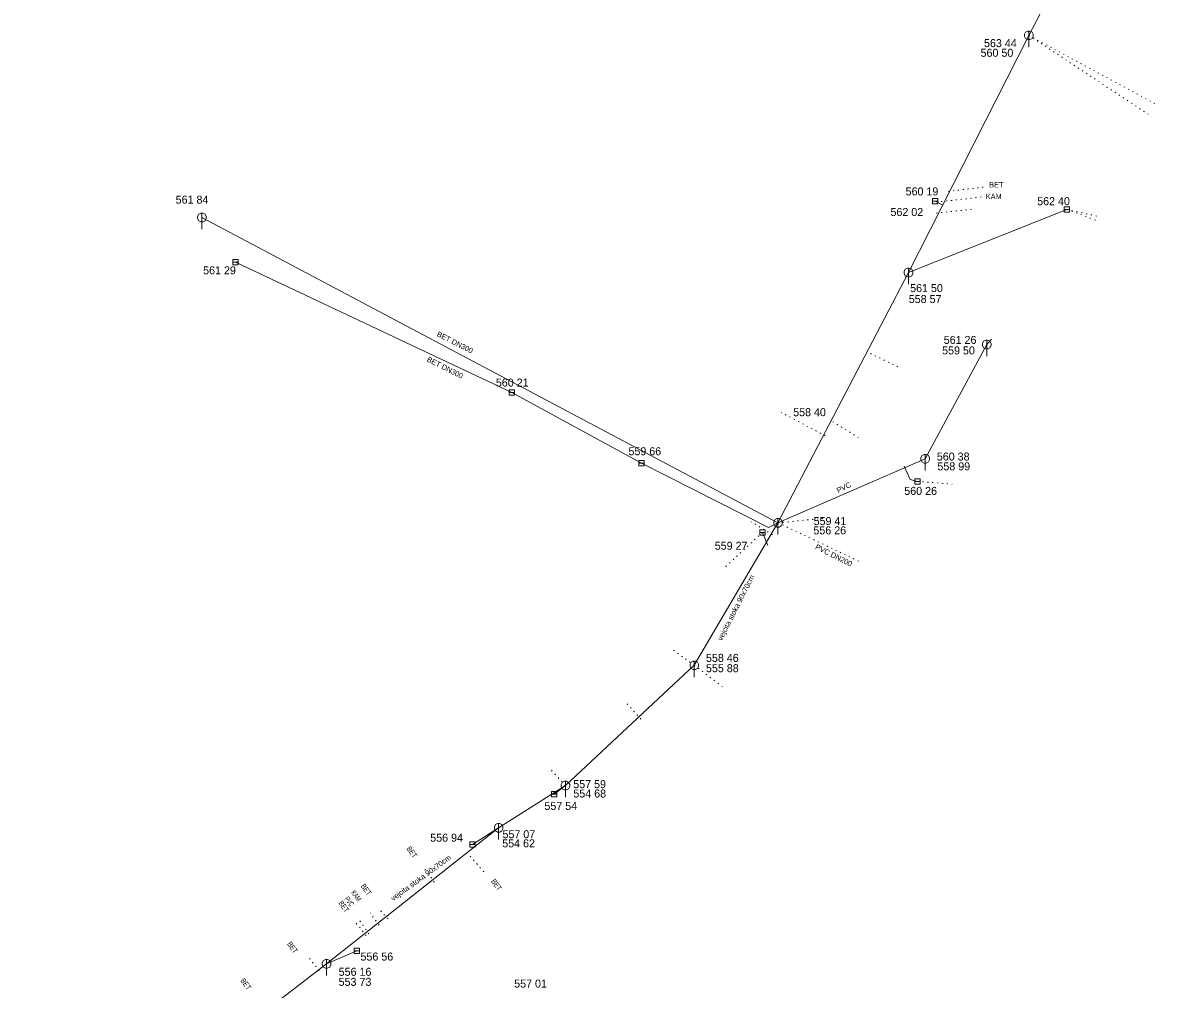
# Model space of a CAD drawing. Extents: x -710806 to -710046, y -1116920 to -1116046.
# Drawn here: x -710401.2 to -710295, y -1116469 to -1116378.5 of the extents above; entities that cross this region are included whole.
import ezdxf
from ezdxf.enums import TextEntityAlignment as Align

# ---------------------------------------------------------------- set-up
doc = ezdxf.new("R2010")
doc.units = 0
doc.header["$LTSCALE"] = 0.3
doc.linetypes.add('DOTTED', pattern=[1.5, 0.3, -1.2])
for name, color, linetype, lineweight in [('40', 7, 'Continuous', 13), ('41', 7, 'Continuous', 13), ('45', 7, 'DOTTED', 13)]:
    doc.layers.add(name, color=color, linetype=linetype, lineweight=lineweight)
doc.layers.add('43', color=7, linetype='Continuous')
doc.layers.add('44', color=7, linetype='Continuous')

msp = doc.modelspace()

# ---------------------------------------------------------------- linework, layer by layer
at = {"layer": '40'}
for points in [[(-710330.414, -1116425.31), (-710318.181, -1116401.863), (-710306.903, -1116379.643), (-710298.116, -1116362.85), (-710302.211, -1116354.462), (-710301.898, -1116344.085), (-710299.298, -1116328.891)], [(-710350.334, -1116449.934), (-710338.256, -1116438.666), (-710330.414, -1116425.31), (-710384.403, -1116396.708)], [(-710381.248, -1116400.906), (-710355.346, -1116413.11), (-710343.193, -1116419.719), (-710331.29, -1116425.767), (-710330.414, -1116425.31), (-710316.618, -1116419.317), (-710310.847, -1116408.606), (-710310.408, -1116408.122)], [(-710401.2, -1116488.589), (-710372.719, -1116466.635), (-710356.594, -1116453.887), (-710350.334, -1116449.934)]]:
    msp.add_lwpolyline(points, dxfattribs=at)
at = {"layer": '41'}
for p, q in [((-710306.903, -1116379.243), (-710306.903, -1116380.743)), ((-710315.418, -1116394.944), (-710315.918, -1116394.944)), ((-710315.918, -1116394.944), (-710315.918, -1116395.444)), ((-710315.418, -1116395.444), (-710315.418, -1116394.944)), ((-710315.418, -1116395.194), (-710315.918, -1116395.194)), ((-710315.918, -1116395.444), (-710315.418, -1116395.444)), ((-710303.083, -1116395.705), (-710303.583, -1116395.705)), ((-710303.583, -1116395.705), (-710303.583, -1116396.205)), ((-710303.083, -1116395.955), (-710303.583, -1116395.955)), ((-710303.083, -1116396.205), (-710303.083, -1116395.705)), ((-710384.403, -1116396.308), (-710384.403, -1116397.808)), ((-710303.583, -1116396.205), (-710303.083, -1116396.205)), ((-710380.998, -1116400.656), (-710381.498, -1116400.656)), ((-710381.498, -1116400.656), (-710381.498, -1116401.156)), ((-710380.998, -1116400.906), (-710381.498, -1116400.906)), ((-710381.498, -1116401.156), (-710380.998, -1116401.156)), ((-710380.998, -1116401.156), (-710380.998, -1116400.656)), ((-710318.181, -1116401.463), (-710318.181, -1116402.963)), ((-710310.847, -1116408.206), (-710310.847, -1116409.706)), ((-710355.096, -1116412.86), (-710355.596, -1116412.86)), ((-710355.596, -1116412.86), (-710355.596, -1116413.36)), ((-710355.096, -1116413.11), (-710355.596, -1116413.11)), ((-710355.096, -1116413.36), (-710355.096, -1116412.86)), ((-710355.596, -1116413.36), (-710355.096, -1116413.36)), ((-710342.943, -1116419.469), (-710343.443, -1116419.469)), ((-710343.443, -1116419.469), (-710343.443, -1116419.969)), ((-710342.943, -1116419.969), (-710342.943, -1116419.469)), ((-710316.618, -1116418.917), (-710316.618, -1116420.417)), ((-710342.943, -1116419.719), (-710343.443, -1116419.719)), ((-710343.443, -1116419.969), (-710342.943, -1116419.969)), ((-710317.087, -1116421.193), (-710317.587, -1116421.193)), ((-710317.587, -1116421.193), (-710317.587, -1116421.693)), ((-710317.087, -1116421.443), (-710317.587, -1116421.443)), ((-710317.087, -1116421.693), (-710317.087, -1116421.193)), ((-710317.587, -1116421.693), (-710317.087, -1116421.693)), ((-710330.414, -1116424.91), (-710330.414, -1116426.41)), ((-710331.62, -1116425.959), (-710332.12, -1116425.959)), ((-710332.12, -1116425.959), (-710332.12, -1116426.459)), ((-710331.62, -1116426.209), (-710332.12, -1116426.209)), ((-710332.12, -1116426.459), (-710331.62, -1116426.459)), ((-710331.62, -1116426.459), (-710331.62, -1116425.959)), ((-710338.256, -1116438.266), (-710338.256, -1116439.766)), ((-710350.334, -1116449.534), (-710350.334, -1116451.034)), ((-710351.141, -1116450.499), (-710351.641, -1116450.499)), ((-710351.641, -1116450.499), (-710351.641, -1116450.999)), ((-710351.141, -1116450.749), (-710351.641, -1116450.749)), ((-710351.641, -1116450.999), (-710351.141, -1116450.999)), ((-710351.141, -1116450.999), (-710351.141, -1116450.499)), ((-710356.594, -1116453.487), (-710356.594, -1116454.987)), ((-710358.804, -1116455.195), (-710359.304, -1116455.195)), ((-710359.304, -1116455.195), (-710359.304, -1116455.695)), ((-710358.804, -1116455.445), (-710359.304, -1116455.445)), ((-710358.804, -1116455.695), (-710358.804, -1116455.195)), ((-710359.304, -1116455.695), (-710358.804, -1116455.695)), ((-710369.625, -1116465.17), (-710370.125, -1116465.17)), ((-710370.125, -1116465.17), (-710370.125, -1116465.67)), ((-710369.625, -1116465.42), (-710370.125, -1116465.42)), ((-710370.125, -1116465.67), (-710369.625, -1116465.67)), ((-710369.625, -1116465.67), (-710369.625, -1116465.17)), ((-710372.719, -1116466.235), (-710372.719, -1116467.735))]:
    msp.add_line(p, q, dxfattribs=at)
for points in [[(-710307.303, -1116379.743), (-710307.303, -1116379.543), (-710307.203, -1116379.343), (-710307.003, -1116379.243), (-710306.803, -1116379.243), (-710306.603, -1116379.343), (-710306.503, -1116379.543), (-710306.503, -1116379.743), (-710306.603, -1116379.943), (-710306.803, -1116380.043), (-710307.003, -1116380.043), (-710307.203, -1116379.943)], [(-710384.803, -1116396.808), (-710384.803, -1116396.608), (-710384.703, -1116396.408), (-710384.503, -1116396.308), (-710384.303, -1116396.308), (-710384.103, -1116396.408), (-710384.003, -1116396.608), (-710384.003, -1116396.808), (-710384.103, -1116397.008), (-710384.303, -1116397.108), (-710384.503, -1116397.108), (-710384.703, -1116397.008)], [(-710318.581, -1116401.963), (-710318.581, -1116401.763), (-710318.481, -1116401.563), (-710318.281, -1116401.463), (-710318.081, -1116401.463), (-710317.881, -1116401.563), (-710317.781, -1116401.763), (-710317.781, -1116401.963), (-710317.881, -1116402.163), (-710318.081, -1116402.263), (-710318.281, -1116402.263), (-710318.481, -1116402.163)], [(-710311.247, -1116408.706), (-710311.247, -1116408.506), (-710311.147, -1116408.306), (-710310.947, -1116408.206), (-710310.747, -1116408.206), (-710310.547, -1116408.306), (-710310.447, -1116408.506), (-710310.447, -1116408.706), (-710310.547, -1116408.906), (-710310.747, -1116409.006), (-710310.947, -1116409.006), (-710311.147, -1116408.906)], [(-710317.018, -1116419.417), (-710317.018, -1116419.217), (-710316.918, -1116419.017), (-710316.718, -1116418.917), (-710316.518, -1116418.917), (-710316.318, -1116419.017), (-710316.218, -1116419.217), (-710316.218, -1116419.417), (-710316.318, -1116419.617), (-710316.518, -1116419.717), (-710316.718, -1116419.717), (-710316.918, -1116419.617)], [(-710330.814, -1116425.41), (-710330.814, -1116425.21), (-710330.714, -1116425.01), (-710330.514, -1116424.91), (-710330.314, -1116424.91), (-710330.114, -1116425.01), (-710330.014, -1116425.21), (-710330.014, -1116425.41), (-710330.114, -1116425.61), (-710330.314, -1116425.71), (-710330.514, -1116425.71), (-710330.714, -1116425.61)], [(-710338.656, -1116438.766), (-710338.656, -1116438.566), (-710338.556, -1116438.366), (-710338.356, -1116438.266), (-710338.156, -1116438.266), (-710337.956, -1116438.366), (-710337.856, -1116438.566), (-710337.856, -1116438.766), (-710337.956, -1116438.966), (-710338.156, -1116439.066), (-710338.356, -1116439.066), (-710338.556, -1116438.966)], [(-710350.734, -1116450.034), (-710350.734, -1116449.834), (-710350.634, -1116449.634), (-710350.434, -1116449.534), (-710350.234, -1116449.534), (-710350.034, -1116449.634), (-710349.934, -1116449.834), (-710349.934, -1116450.034), (-710350.034, -1116450.234), (-710350.234, -1116450.334), (-710350.434, -1116450.334), (-710350.634, -1116450.234)], [(-710356.994, -1116453.987), (-710356.994, -1116453.787), (-710356.894, -1116453.587), (-710356.694, -1116453.487), (-710356.494, -1116453.487), (-710356.294, -1116453.587), (-710356.194, -1116453.787), (-710356.194, -1116453.987), (-710356.294, -1116454.187), (-710356.494, -1116454.287), (-710356.694, -1116454.287), (-710356.894, -1116454.187)], [(-710373.119, -1116466.735), (-710373.119, -1116466.535), (-710373.019, -1116466.335), (-710372.819, -1116466.235), (-710372.619, -1116466.235), (-710372.419, -1116466.335), (-710372.319, -1116466.535), (-710372.319, -1116466.735), (-710372.419, -1116466.935), (-710372.619, -1116467.035), (-710372.819, -1116467.035), (-710373.019, -1116466.935)]]:
    msp.add_lwpolyline(points, close=True, dxfattribs=at)
at = {"layer": '45'}
for p, q in [((-710306.903, -1116379.643), (-710295.711, -1116387.042)), ((-710306.903, -1116379.643), (-710295.046, -1116386.063)), ((-710314.466, -1116394.262), (-710310.932, -1116393.84)), ((-710315.115, -1116395.225), (-710311.161, -1116394.765)), ((-710315.577, -1116396.297), (-710312.139, -1116395.928)), ((-710303.333, -1116395.955), (-710300.621, -1116396.964)), ((-710303.333, -1116395.955), (-710300.413, -1116396.601)), ((-710321.75, -1116409.457), (-710319.093, -1116410.732)), ((-710325.996, -1116417.159), (-710330.091, -1116414.983)), ((-710325.281, -1116415.845), (-710322.878, -1116417.315)), ((-710317.337, -1116421.443), (-710314.074, -1116421.685)), ((-710330.924, -1116426.426), (-710332.912, -1116425.224)), ((-710330.414, -1116425.31), (-710326.22, -1116424.907)), ((-710330.414, -1116425.31), (-710322.58, -1116429.039)), ((-710331.87, -1116426.209), (-710335.451, -1116429.57)), ((-710338.256, -1116438.666), (-710340.344, -1116437.159)), ((-710338.256, -1116438.666), (-710335.613, -1116440.665)), ((-710343.25, -1116443.707), (-710344.572, -1116442.259)), ((-710350.334, -1116449.934), (-710351.839, -1116448.293)), ((-710359.249, -1116456.542), (-710357.764, -1116458.288)), ((-710362.625, -1116458.975), (-710363.589, -1116457.673)), ((-710367.803, -1116463.009), (-710368.628, -1116461.876)), ((-710366.958, -1116462.43), (-710367.866, -1116461.434)), ((-710369.004, -1116463.988), (-710369.955, -1116462.81)), ((-710368.747, -1116463.829), (-710369.636, -1116462.564)), ((-710373.409, -1116467.289), (-710374.404, -1116466.005))]:
    msp.add_line(p, q, dxfattribs=at)
at = {"layer": '45', "linetype": 'Continuous'}
for p, q in [((-710303.333, -1116395.955), (-710318.181, -1116401.863)), ((-710315.668, -1116395.194), (-710314.974, -1116395.545)), ((-710331.378, -1116427.434), (-710331.87, -1116426.209)), ((-710351.391, -1116450.749), (-710350.334, -1116449.934)), ((-710359.054, -1116455.445), (-710356.594, -1116453.887)), ((-710369.875, -1116465.42), (-710372.719, -1116466.635))]:
    msp.add_line(p, q, dxfattribs=at)
msp.add_lwpolyline([(-710318.571, -1116420.002), (-710318.023, -1116421.263), (-710317.337, -1116421.443)], dxfattribs=at)

# ---------------------------------------------------------------- texts
at = {"layer": '43'}
for s, p in [('563 44 ', (-710309.4302, -1116380.747)), ('560 19 ', (-710316.7772, -1116394.639)), ('561 84 ', (-710385.1872, -1116395.411)), ('562 40 ', (-710304.4482, -1116395.557)), ('562 02 ', (-710318.1952, -1116396.571)), ('561 29 ', (-710382.6132, -1116402.035)), ('561 50 ', (-710316.3522, -1116403.699)), ('561 26 ', (-710313.2052, -1116408.554)), ('560 21 ', (-710355.1782, -1116412.55)), ('558 40 ', (-710327.3172, -1116415.325)), ('559 66 ', (-710342.7522, -1116418.985)), ('560 38 ', (-710313.8522, -1116419.481)), ('560 26 ', (-710316.9022, -1116422.699)), ('559 41 ', (-710325.4012, -1116425.525)), ('559 27 ', (-710334.6652, -1116427.838)), ('558 46 ', (-710335.4882, -1116438.346)), ('557 59 ', (-710347.9272, -1116450.175)), ('557 54 ', (-710350.6282, -1116452.217)), ('556 94 ', (-710361.3302, -1116455.19)), ('557 07 ', (-710354.5582, -1116454.865)), ('556 56 ', (-710367.8662, -1116466.328)), ('556 16 ', (-710369.9092, -1116467.755)), ('557 01 ', (-710353.4622, -1116468.863))]:
    msp.add_text(s, height=0.75, dxfattribs=at).set_placement(p, align=Align.CENTER)
for s, p in [('560 50', (-710311.425, -1116381.651)), ('558 57', (-710318.156, -1116404.721)), ('559 50', (-710315.029, -1116409.537)), ('558 99', (-710315.47, -1116420.397)), ('556 26', (-710327.093, -1116426.394)), ('555 88', (-710337.16, -1116439.31)), ('554 68', (-710349.589, -1116451.053)), ('554 62', (-710356.257, -1116455.719)), ('553 73', (-710371.586, -1116468.696))]:
    msp.add_text(s, height=0.75, dxfattribs=at).set_placement(p)
at = {"layer": '44'}
for s, p in [('BET', (-710310.622, -1116393.899)), ('KAM', (-710310.94, -1116394.99))]:
    msp.add_text(s, height=0.5, dxfattribs=at).set_placement(p)
for s, rotation, p in [('BET DN300', 333, (-710362.44, -1116407.798)), ('BET DN300', 333, (-710363.367, -1116410.162)), ('PVC', 27, (-710324.762, -1116422.552)), ('PVC DN200', 333, (-710326.975, -1116427.735)), ('vejcita stoka 90x70cm', 63, (-710335.668, -1116436.398)), ('vejcita stoka 90x70cm', 36, (-710366.477, -1116460.777))]:
    msp.add_text(s, height=0.5, rotation=rotation, dxfattribs=at).set_placement(p)
for s, width, p in [('BET', 0.7, (-710365.257, -1116455.856)), ('BET', 0.7, (-710357.329, -1116458.909)), ('KAM', 0.6, (-710370.461, -1116459.968)), ('BET', 0.7, (-710369.54, -1116459.364)), ('BET', 0.7, (-710371.635, -1116460.959)), ('PVC ', 0.55, (-710371.076, -1116460.557)), ('BET', 0.7, (-710376.442, -1116464.786)), ('BET', 0.7, (-710380.813, -1116468.221))]:
    msp.add_text(s, height=0.5, rotation=306, dxfattribs=dict(at, width=width)).set_placement(p)

doc.saveas('drawing.dxf')
